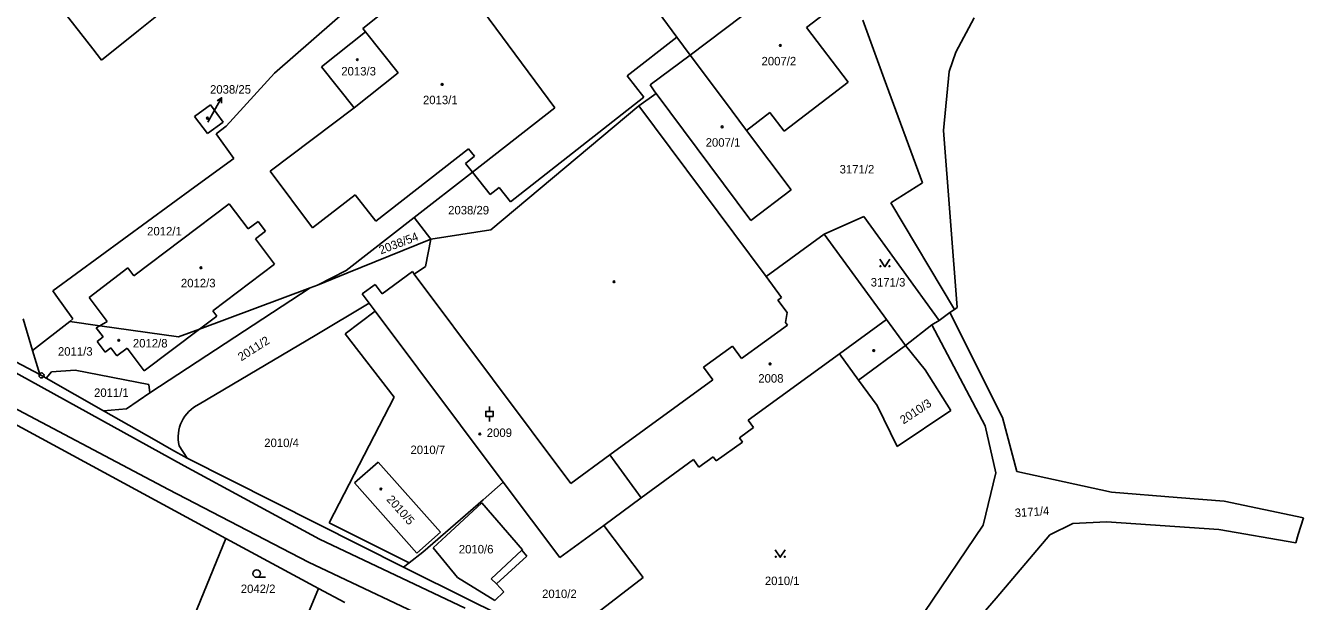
# Model space of a CAD drawing. Extents: x -736345 to -729997, y -1130177 to -1122501.
# Drawn here: x -732763.4 to -732507.1, y -1127764.4 to -1127649.1 of the extents above; entities that cross this region are included whole.
import ezdxf

# ---------------------------------------------------------------- set-up
doc = ezdxf.new("R2010")
doc.units = 0
for name, color, linetype in [('Vrstva 1', 7, 'Continuous'), ('Vrstva 16', 7, 'Continuous'), ('Vrstva 18', 7, 'Continuous'), ('Vrstva 19', 7, 'Continuous'), ('Vrstva 25', 7, 'Continuous'), ('Vrstva 4', 7, 'Continuous')]:
    doc.layers.add(name, color=color, linetype=linetype)

msp = doc.modelspace()

# ---------------------------------------------------------------- linework, layer by layer
at = {"layer": 'Vrstva 1'}
for points in [[(-732713.41, -1127658.6), (-732689.75, -1127637.93)], [(-732677.09, -1127638.76), (-732657.19, -1127665.57)], [(-732695.73, -1127649.69), (-732684.14, -1127640.42)], [(-732630.07, -1127655.03), (-732612.64, -1127641.79)], [(-732755.89, -1127646.07), (-732749.87, -1127653.78)], [(-732733.99, -1127644.77), (-732740.72, -1127650.11)], [(-732637.46, -1127645.1), (-732632.78, -1127651.39)], [(-732606.76, -1127649.49), (-732601.93, -1127645.79)], [(-732591.18, -1127659.76), (-732595.46, -1127648.04)], [(-732576.78, -1127654.45), (-732573.16, -1127647.52)], [(-732740.72, -1127650.11), (-732748.14, -1127656)], [(-732703.99, -1127657.38), (-732695.2, -1127650.36)], [(-732695.2, -1127650.36), (-732695.73, -1127649.69)], [(-732695.2, -1127650.36), (-732688.64, -1127658.56)], [(-732632.78, -1127651.39), (-732642.72, -1127659.15)], [(-732630.07, -1127655.03), (-732632.78, -1127651.39)], [(-732598.41, -1127660.42), (-732606.76, -1127649.49)], [(-732749.87, -1127653.78), (-732748.14, -1127656)], [(-732630.07, -1127655.03), (-732638.12, -1127660.98)], [(-732630.07, -1127655.03), (-732623.21, -1127664.19)], [(-732578.17, -1127658.29), (-732576.78, -1127654.45)], [(-732723.11, -1127669.27), (-732713.41, -1127658.6)], [(-732697.43, -1127665.58), (-732703.99, -1127657.38)], [(-732688.64, -1127658.56), (-732697.43, -1127665.58)], [(-732639.35, -1127663.46), (-732642.72, -1127659.15)], [(-732579.25, -1127670.13), (-732578.17, -1127658.29)], [(-732638.12, -1127660.98), (-732637.17, -1127662.35)], [(-732611.26, -1127670.24), (-732598.41, -1127660.42)], [(-732583.51, -1127680.57), (-732591.18, -1127659.76)], [(-732666.1, -1127684.39), (-732639.35, -1127663.46)], [(-732640.37, -1127665.19), (-732636.91, -1127662.72)], [(-732637.17, -1127662.35), (-732636.91, -1127662.72)], [(-732636.91, -1127662.72), (-732617.92, -1127688.11)], [(-732623.21, -1127664.19), (-732618.79, -1127670.1)], [(-732726.27, -1127664.97), (-732729.46, -1127667.32)], [(-732723.72, -1127668.43), (-732726.27, -1127664.97)], [(-732714.28, -1127678.27), (-732697.43, -1127665.58)], [(-732657.19, -1127665.57), (-732673.76, -1127678.46)], [(-732670.04, -1127690.03), (-732640.37, -1127665.19)], [(-732640.37, -1127665.19), (-732621.32, -1127690.66)], [(-732614.11, -1127666.52), (-732618.79, -1127670.1)], [(-732611.26, -1127670.24), (-732614.11, -1127666.52)], [(-732729.46, -1127667.32), (-732726.86, -1127670.71)], [(-732726.86, -1127670.71), (-732723.72, -1127668.43)], [(-732725.13, -1127670.76), (-732723.11, -1127669.27)], [(-732721.58, -1127675.69), (-732725.13, -1127670.76)], [(-732609.8, -1127682.02), (-732618.79, -1127670.1)], [(-732579.25, -1127670.13), (-732576.56, -1127705.57)], [(-732674.52, -1127673.77), (-732693.11, -1127688.3)], [(-732673.34, -1127675.26), (-732674.52, -1127673.77)], [(-732729.41, -1127681.41), (-732721.58, -1127675.69)], [(-732675.15, -1127676.7), (-732673.34, -1127675.26)], [(-732673.76, -1127678.46), (-732675.15, -1127676.7)], [(-732705.78, -1127689.64), (-732714.28, -1127678.27)], [(-732673.76, -1127678.46), (-732685.45, -1127687.55)], [(-732673.76, -1127678.46), (-732670.19, -1127682.95)], [(-732738.92, -1127688.37), (-732729.41, -1127681.41)], [(-732670.19, -1127682.95), (-732668.38, -1127681.52)], [(-732668.38, -1127681.52), (-732666.1, -1127684.39)], [(-732609.8, -1127682.02), (-732617.92, -1127688.11)], [(-732589.85, -1127684.62), (-732583.51, -1127680.57)], [(-732722.5, -1127684.78), (-732741.62, -1127699.2)], [(-732718.72, -1127689.82), (-732722.5, -1127684.78)], [(-732697.27, -1127682.99), (-732705.78, -1127689.64)], [(-732693.11, -1127688.3), (-732697.27, -1127682.99)], [(-732577.1, -1127705.96), (-732589.85, -1127684.62)], [(-732685.45, -1127687.55), (-732699.03, -1127698.13)], [(-732685.45, -1127687.55), (-732682.06, -1127691.9)], [(-732595.26, -1127687.32), (-732603.21, -1127690.85)], [(-732580.17, -1127708.15), (-732595.26, -1127687.32)], [(-732757.9, -1127702.25), (-732738.92, -1127688.37)], [(-732716.72, -1127688.32), (-732718.72, -1127689.82)], [(-732715.22, -1127690.3), (-732716.72, -1127688.32)], [(-732670.04, -1127690.03), (-732682.06, -1127691.9)], [(-732717.23, -1127691.81), (-732715.22, -1127690.3)], [(-732713.4, -1127696.91), (-732717.23, -1127691.81)], [(-732682.06, -1127691.9), (-732698.96, -1127698.71)], [(-732683.13, -1127697.38), (-732682.06, -1127691.9)], [(-732621.32, -1127690.66), (-732614.85, -1127699.38)], [(-732603.21, -1127690.85), (-732614.85, -1127699.38)], [(-732603.21, -1127690.85), (-732590.71, -1127707.94)], [(-732742.81, -1127697.62), (-732750.6, -1127703.53)], [(-732741.62, -1127699.2), (-732742.81, -1127697.62)], [(-732725.83, -1127706.24), (-732713.4, -1127696.91)], [(-732685.4, -1127698.87), (-732683.13, -1127697.38)], [(-732699.03, -1127698.13), (-732704.82, -1127701.07)], [(-732698.96, -1127698.71), (-732704.82, -1127701.07)], [(-732691.84, -1127702.85), (-732685.79, -1127698.35)], [(-732685.79, -1127698.35), (-732685.4, -1127698.87)], [(-732654.02, -1127740.82), (-732685.4, -1127698.87)], [(-732757.28, -1127703.11), (-732757.9, -1127702.25)], [(-732706.27, -1127701.65), (-732738.43, -1127722.65)], [(-732706.27, -1127701.65), (-732728.49, -1127709.92)], [(-732704.82, -1127701.07), (-732706.27, -1127701.65)], [(-732695.82, -1127702.85), (-732693.23, -1127700.99)], [(-732694.44, -1127704.69), (-732695.82, -1127702.85)], [(-732693.23, -1127700.99), (-732691.84, -1127702.85)], [(-732753.89, -1127707.85), (-732757.28, -1127703.11)], [(-732750.6, -1127703.53), (-732746.98, -1127708.37)], [(-732705.31, -1127711.14), (-732694.44, -1127704.69)], [(-732694.44, -1127704.69), (-732693.23, -1127706.31)], [(-732760.47, -1127719.01), (-732783.46, -1127706.91)], [(-732763.85, -1127707.84), (-732761.93, -1127714.17)], [(-732754.46, -1127708.39), (-732753.89, -1127707.85)], [(-732728.49, -1127709.92), (-732725.02, -1127707.32)], [(-732725.02, -1127707.32), (-732725.83, -1127706.24)], [(-732693.23, -1127706.31), (-732699.29, -1127710.81)], [(-732667.57, -1127740.52), (-732693.23, -1127706.31)], [(-732590.71, -1127707.94), (-732586.9, -1127713.17)], [(-732580.17, -1127708.15), (-732578.01, -1127706.57)], [(-732578.01, -1127706.57), (-732577.1, -1127705.96)], [(-732578.01, -1127706.57), (-732567.46, -1127727.58)], [(-732576.56, -1127705.57), (-732577.1, -1127705.96)], [(-732754.46, -1127708.39), (-732761.93, -1127714.17)], [(-732748.47, -1127709.24), (-732754.46, -1127708.39)], [(-732748.47, -1127709.24), (-732749.2, -1127709.66)], [(-732749.2, -1127709.66), (-732747.77, -1127711.47)], [(-732746.98, -1127708.37), (-732748.47, -1127709.24)], [(-732732.65, -1127711.47), (-732748.47, -1127709.24)], [(-732739.6, -1127718.22), (-732728.49, -1127709.92)], [(-732728.49, -1127709.92), (-732732.65, -1127711.47)], [(-732581.6, -1127709.04), (-732586.9, -1127713.17)], [(-732581.6, -1127709.04), (-732580.17, -1127708.15)], [(-732570.9, -1127729.26), (-732581.6, -1127709.04)], [(-732747.77, -1127711.47), (-732749.02, -1127712.4)], [(-732749.02, -1127712.4), (-732747.42, -1127714.54)], [(-732728.56, -1127724.95), (-732705.31, -1127711.14)], [(-732699.29, -1127710.81), (-732689.45, -1127723.54)], [(-732586.9, -1127713.17), (-732596.33, -1127720.15)], [(-732586.9, -1127713.17), (-732582.94, -1127718.08)], [(-732761.93, -1127714.17), (-732760.47, -1127719.01)], [(-732747.42, -1127714.54), (-732746.23, -1127713.65)], [(-732746.23, -1127713.65), (-732745.03, -1127715.25)], [(-732745.03, -1127715.25), (-732742.98, -1127713.72)], [(-732742.98, -1127713.72), (-732739.6, -1127718.22)], [(-732618.46, -1127728.13), (-732600.15, -1127714.87)], [(-732600.15, -1127714.87), (-732596.33, -1127720.15)], [(-732758.13, -1127718.48), (-732753.42, -1127718.1)], [(-732753.42, -1127718.1), (-732738.6, -1127720.99)], [(-732582.94, -1127718.08), (-732577.78, -1127726.22)], [(-732760.47, -1127719.01), (-732760.15, -1127719.18)], [(-732760.15, -1127719.18), (-732759.2, -1127719.72)], [(-732759.2, -1127719.72), (-732758.13, -1127718.48)], [(-732747.75, -1127726.23), (-732759.2, -1127719.72)], [(-732596.33, -1127720.15), (-732592.61, -1127725.18)], [(-732738.43, -1127722.65), (-732743.08, -1127725.88)], [(-732738.6, -1127720.99), (-732738.43, -1127722.65)], [(-732723.2, -1127751.8), (-732774.42, -1127724.13)], [(-732743.08, -1127725.88), (-732747.75, -1127726.23)], [(-732689.45, -1127723.54), (-732702.47, -1127748.69)], [(-732592.61, -1127725.18), (-732588.6, -1127733.39)], [(-732747.75, -1127726.23), (-732737.56, -1127732.02)], [(-732617.39, -1127729.63), (-732618.46, -1127728.13)], [(-732588.6, -1127733.39), (-732577.78, -1127726.22)], [(-732567.46, -1127727.58), (-732564.58, -1127738.39)], [(-732620.19, -1127731.65), (-732617.39, -1127729.63)], [(-732568.76, -1127738.71), (-732570.9, -1127729.26)], [(-732737.56, -1127732.02), (-732734.08, -1127733.99)], [(-732732.55, -1127733.24), (-732730.95, -1127735.77)], [(-732624.88, -1127736.28), (-732619.58, -1127732.51)], [(-732619.58, -1127732.51), (-732620.19, -1127731.65)], [(-732734.08, -1127733.99), (-732730.95, -1127735.77)], [(-732687.53, -1127757.55), (-732730.95, -1127735.77)], [(-732654.02, -1127740.82), (-732646.17, -1127735.09)], [(-732646.17, -1127735.09), (-732639.88, -1127743.67)], [(-732639.88, -1127743.67), (-732629.4, -1127735.99)], [(-732629.4, -1127735.99), (-732628.31, -1127737.51)], [(-732628.31, -1127737.51), (-732625.47, -1127735.46)], [(-732625.47, -1127735.46), (-732624.88, -1127736.28)], [(-732692.66, -1127736.52), (-732697.36, -1127740.7)], [(-732692.66, -1127736.52), (-732680.13, -1127750.59)], [(-732571.35, -1127749.15), (-732568.76, -1127738.71)], [(-732564.58, -1127738.39), (-732545.58, -1127742.53)], [(-732684.87, -1127754.77), (-732697.36, -1127740.7)], [(-732667.57, -1127740.52), (-732671.62, -1127744.06)], [(-732656.22, -1127755.66), (-732667.57, -1127740.52)], [(-732639.88, -1127743.67), (-732647.38, -1127749.23)], [(-732545.58, -1127742.53), (-732532.41, -1127743.62)], [(-732532.41, -1127743.62), (-732522.97, -1127744.37)], [(-732671.62, -1127744.06), (-732683.71, -1127754.59)], [(-732679.01, -1127751.28), (-732671.85, -1127744.69)], [(-732663.73, -1127754.07), (-732671.85, -1127744.69)], [(-732522.97, -1127744.37), (-732507.1, -1127747.7)], [(-732702.47, -1127748.69), (-732686.45, -1127756.71)], [(-732553.35, -1127748.82), (-732557.95, -1127751.09)], [(-732546.61, -1127748.48), (-732553.35, -1127748.82)], [(-732524.05, -1127750.01), (-732546.61, -1127748.48)], [(-732507.1, -1127747.7), (-732508.19, -1127751.03)], [(-732680.13, -1127750.59), (-732684.87, -1127754.77)], [(-732681.64, -1127753.7), (-732679.01, -1127751.28)], [(-732647.38, -1127749.23), (-732656.22, -1127755.66)], [(-732647.38, -1127749.23), (-732639.53, -1127759.63)], [(-732583.16, -1127766.66), (-732571.35, -1127749.15)], [(-732557.95, -1127751.09), (-732568.7, -1127763.8)], [(-732508.64, -1127752.69), (-732524.05, -1127750.01)], [(-732508.19, -1127751.03), (-732508.64, -1127752.69)], [(-732730.8, -1127770.48), (-732723.2, -1127751.8)], [(-732723.2, -1127751.8), (-732704.62, -1127761.86)], [(-732681.64, -1127753.7), (-732676.74, -1127759.62)], [(-732663.81, -1127754.15), (-732663.73, -1127754.07)], [(-732662.8, -1127755.38), (-732663.81, -1127754.15)], [(-732686.45, -1127756.71), (-732687.53, -1127757.55)], [(-732683.71, -1127754.59), (-732686.45, -1127756.71)], [(-732668.92, -1127760.93), (-732662.8, -1127755.38)], [(-732674.26, -1127764.21), (-732687.53, -1127757.55)], [(-732704.62, -1127761.86), (-732712.33, -1127780.48)], [(-732704.62, -1127761.86), (-732699.33, -1127764.64)], [(-732676.74, -1127759.62), (-732669.23, -1127764.22)], [(-732667.45, -1127762.49), (-732668.92, -1127760.93)], [(-732639.53, -1127759.63), (-732659.27, -1127774.86)], [(-732664.36, -1127769.06), (-732674.26, -1127764.21)], [(-732669.23, -1127764.22), (-732667.45, -1127762.49)], [(-732568.7, -1127763.8), (-732586.46, -1127784.24)]]:
    msp.add_lwpolyline(points, dxfattribs=at)
msp.add_arc((-732725.399, -1127731.577), 7.342, 115.39652, 193.09325, dxfattribs=at)
at = {"layer": 'Vrstva 16'}
msp.add_lwpolyline([(-732726.77, -1127668.42), (-732725.5, -1127666.16)], dxfattribs=at)
at = {"layer": 'Vrstva 25'}
for points in [[(-732725.5, -1127666.16), (-732724.028, -1127663.547)], [(-732724.954, -1127664.173), (-732724.028, -1127663.547), (-732724.083, -1127664.664)], [(-732592.03, -1127695.89), (-732591.03, -1127697.39), (-732590.03, -1127695.89)], [(-732670.33, -1127726.39), (-732670.33, -1127725.39)], [(-732669.58, -1127727.39), (-732671.08, -1127727.39), (-732671.08, -1127726.39), (-732669.58, -1127726.39), (-732669.58, -1127727.39)], [(-732670.33, -1127728.39), (-732670.33, -1127727.39)], [(-732613.01, -1127754.08), (-732612.01, -1127755.58), (-732611.01, -1127754.08)], [(-732717.01, -1127759.6), (-732715.26, -1127759.6)]]:
    msp.add_lwpolyline(points, dxfattribs=at)
for centre, radius in [((-732612, -1127653.07), 0.175), ((-732696.82, -1127655.93), 0.175), ((-732679.81, -1127660.89), 0.175), ((-732726.89, -1127667.64), 0.175), ((-732623.66, -1127669.37), 0.175), ((-732728.19, -1127697.61), 0.175), ((-732591.93, -1127697.29), 0.1), ((-732590.13, -1127697.29), 0.1), ((-732645.36, -1127700.4), 0.175), ((-732744.67, -1127712.14), 0.175), ((-732593.27, -1127714.19), 0.175), ((-732614.05, -1127716.86), 0.175), ((-732760.15, -1127719.18), 0.5), ((-732760.15, -1127719.18), 0.032), ((-732672.25, -1127730.89), 0.175), ((-732692.09, -1127741.92), 0.175), ((-732612.91, -1127755.48), 0.1), ((-732611.11, -1127755.48), 0.1), ((-732717.01, -1127758.85), 0.75)]:
    msp.add_circle(centre, radius, dxfattribs=at)
at = {"layer": 'Vrstva 4'}
for points in [[(-732614.85, -1127699.38), (-732611.78, -1127703.55)], [(-732611.78, -1127703.55), (-732612.53, -1127704.08)], [(-732612.53, -1127704.08), (-732610.66, -1127706.58)], [(-732610.66, -1127706.58), (-732610.93, -1127708.57)], [(-732590.71, -1127707.94), (-732600.15, -1127714.87)], [(-732610.56, -1127709.08), (-732619.77, -1127715.79)], [(-732610.93, -1127708.57), (-732610.56, -1127709.08)], [(-732627.4, -1127717.51), (-732621.59, -1127713.29)], [(-732621.59, -1127713.29), (-732619.77, -1127715.79)], [(-732767.26, -1127717.61), (-732731.54, -1127737.3)], [(-732625.55, -1127720.05), (-732627.4, -1127717.51)], [(-732625.55, -1127720.05), (-732646.17, -1127735.09)], [(-732734.71, -1127742.02), (-732770.66, -1127723.05)], [(-732731.54, -1127737.3), (-732704.4, -1127751.97)], [(-732706.61, -1127756.55), (-732734.71, -1127742.02)], [(-732704.4, -1127751.97), (-732675.23, -1127765.75)], [(-732663.81, -1127754.15), (-732669.96, -1127759.89)], [(-732678.08, -1127770.08), (-732706.61, -1127756.55)], [(-732669.96, -1127759.89), (-732668.92, -1127760.93)]]:
    msp.add_lwpolyline(points, dxfattribs=at)

# ---------------------------------------------------------------- texts
at = {"layer": 'Vrstva 16'}
msp.add_text('2038/25', height=1.7, dxfattribs=at).set_placement((-732726.36, -1127662.73))
at = {"layer": 'Vrstva 18'}
for s, p in [('3171/2', (-732600.11, -1127678.72)), ('2038/29', (-732678.62, -1127686.92)), ('2012/1', (-732738.98, -1127691.13)), ('3171/3', (-732593.88, -1127701.36)), ('2011/3', (-732756.86, -1127715.21)), ('2011/1', (-732749.62, -1127723.47)), ('2010/4', (-732715.49, -1127733.52)), ('2010/7', (-732686.17, -1127734.92)), ('2010/6', (-732676.478, -1127754.82)), ('2042/2', (-732720.2, -1127762.76)), ('2010/1', (-732615.1, -1127761.16)), ('2010/2', (-732659.78, -1127763.76))]:
    msp.add_text(s, height=1.7, dxfattribs=at).set_placement(p)
for s, rotation, p in [('2038/54', 20.90017, (-732692.095, -1127694.942)), ('2011/2', 32.50026, (-732720.099, -1127716.364)), ('2010/3', 33.50027, (-732587.304, -1127729.003)), ('3171/4', 3.80003, (-732564.944, -1127747.568))]:
    msp.add_text(s, height=1.7, rotation=rotation, dxfattribs=at).set_placement(p)
at = {"layer": 'Vrstva 19'}
for s, height, p in [('2007/2', 1.7, (-732615.77, -1127657.07)), ('2013/3', 1.7, (-732700.04, -1127659.09)), ('2013/1', 1.7, (-732683.66, -1127664.84)), ('2038/25', 0.1, (-732726.57, -1127668.22)), ('2007/1', 1.7, (-732626.97, -1127673.36)), ('2012/3', 1.7, (-732732.2, -1127701.52)), ('2012/8', 1.7, (-732741.83, -1127713.57)), ('2008', 1.7, (-732616.42, -1127720.61)), ('2009', 1.7, (-732670.87, -1127731.49))]:
    msp.add_text(s, height=height, dxfattribs=at).set_placement(p)
msp.add_text('2010/5', height=1.7, rotation=311.60248, dxfattribs=at).set_placement((-732691.088, -1127744.076))

doc.saveas('drawing.dxf')
